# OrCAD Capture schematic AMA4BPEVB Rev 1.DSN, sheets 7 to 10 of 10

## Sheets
7 P08: Power Supply Tracker: size Custom
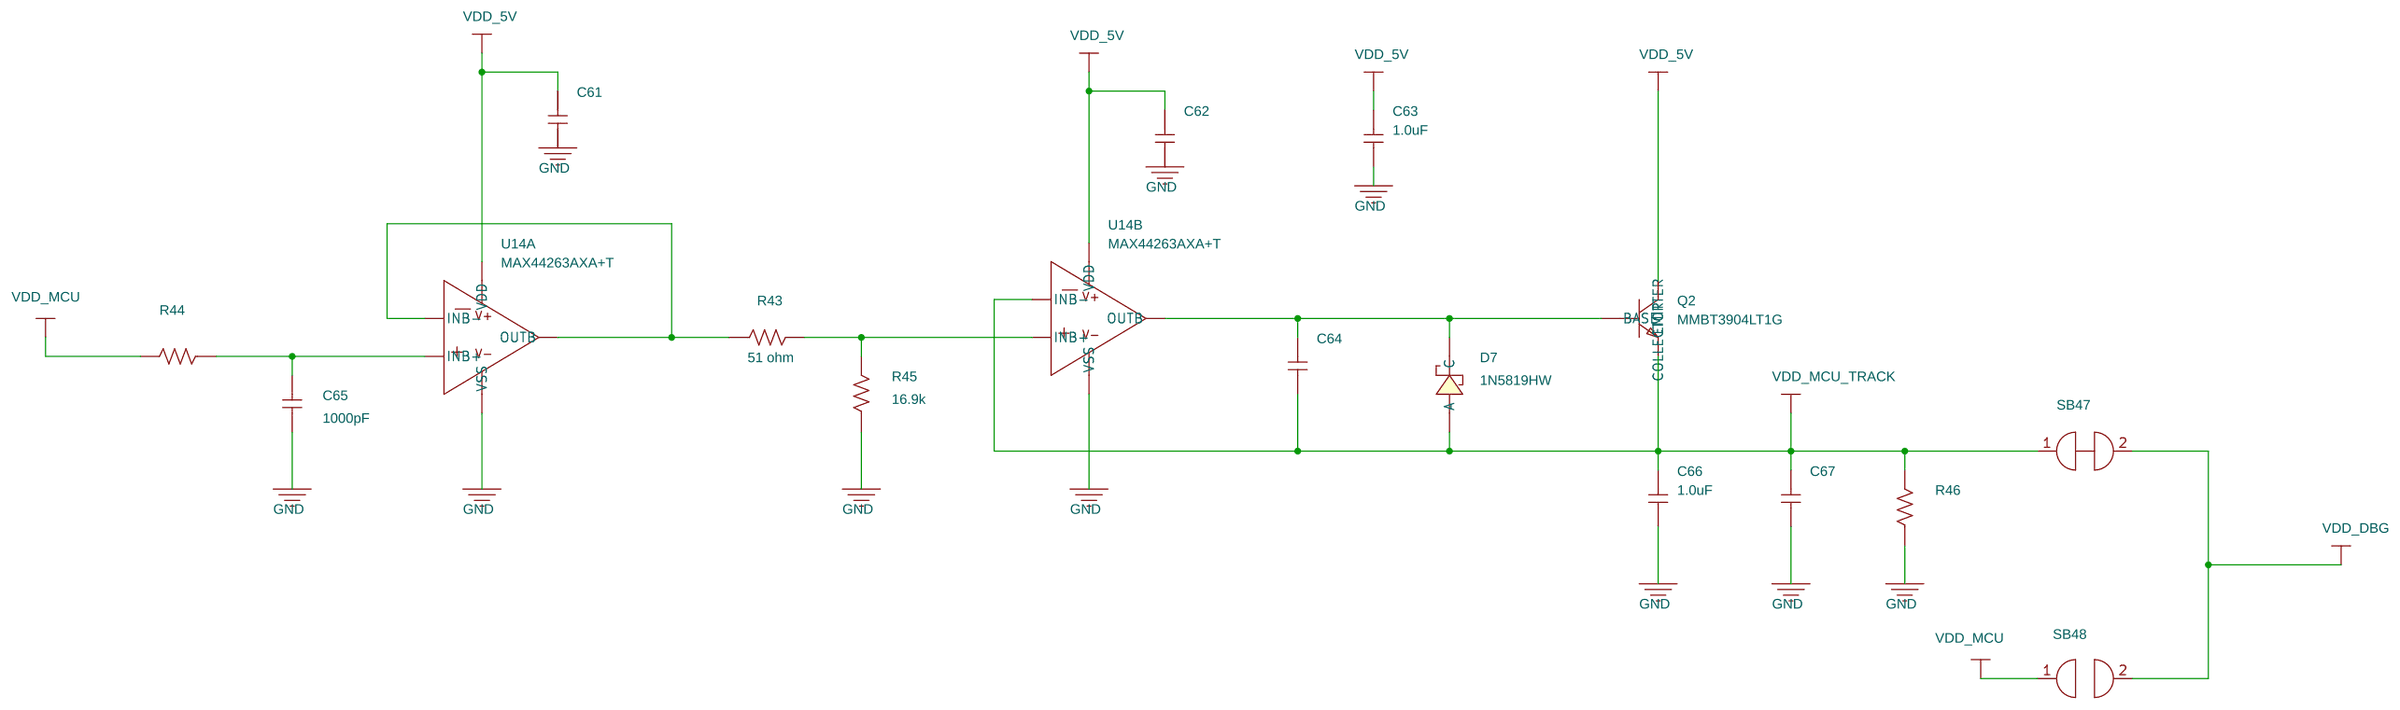
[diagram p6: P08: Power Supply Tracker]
8 P09: Audio Connections: size Custom
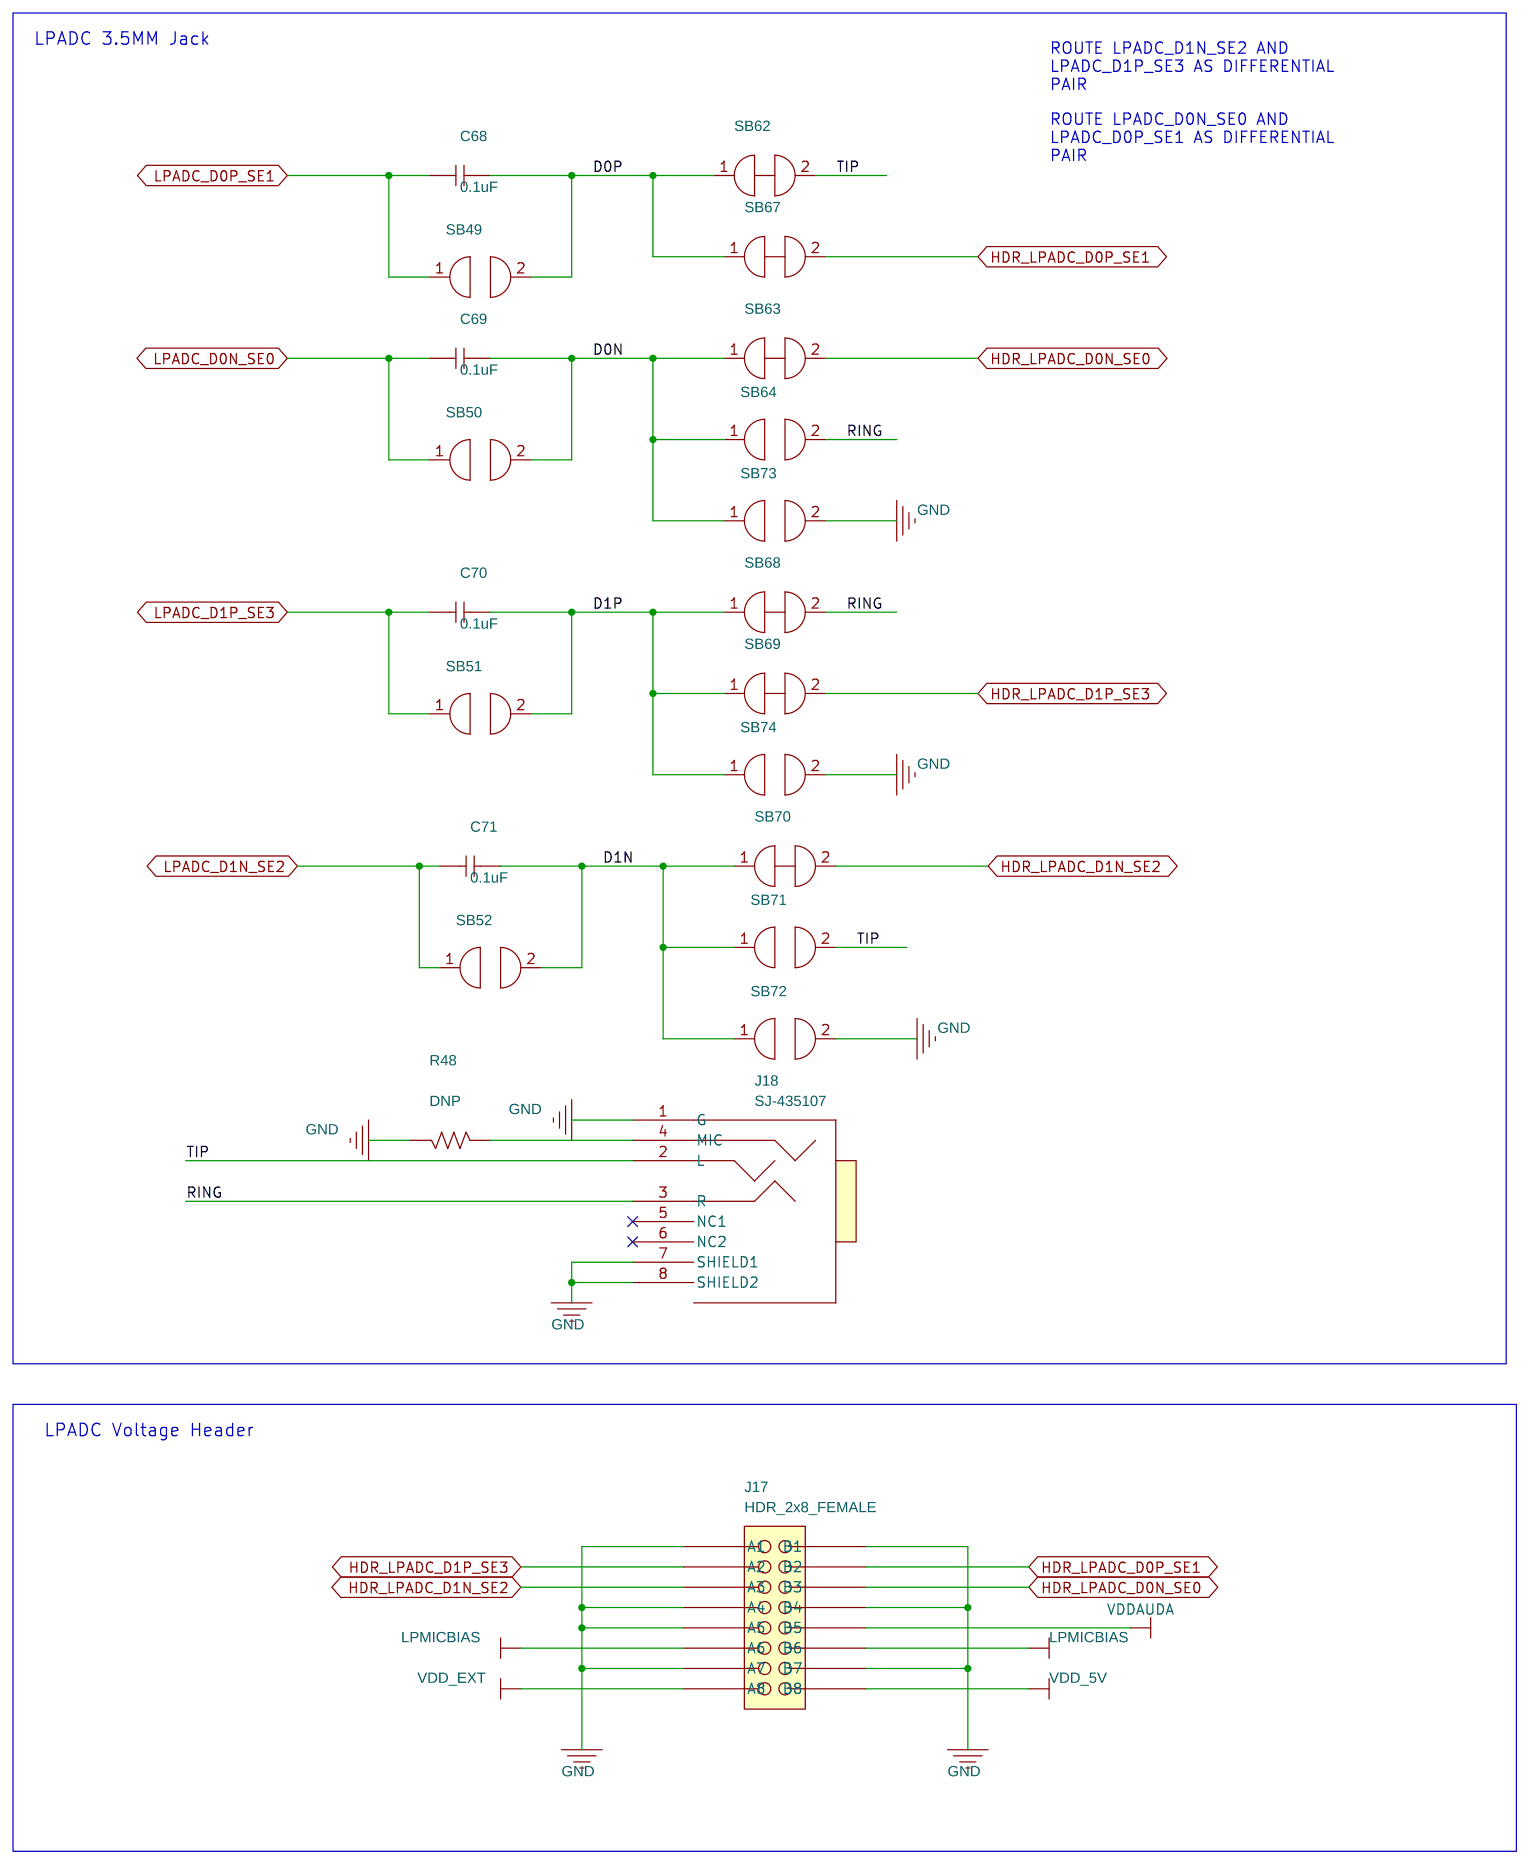
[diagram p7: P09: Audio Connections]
9 P02: Apollo 4 Blue Plus MCU: size Custom
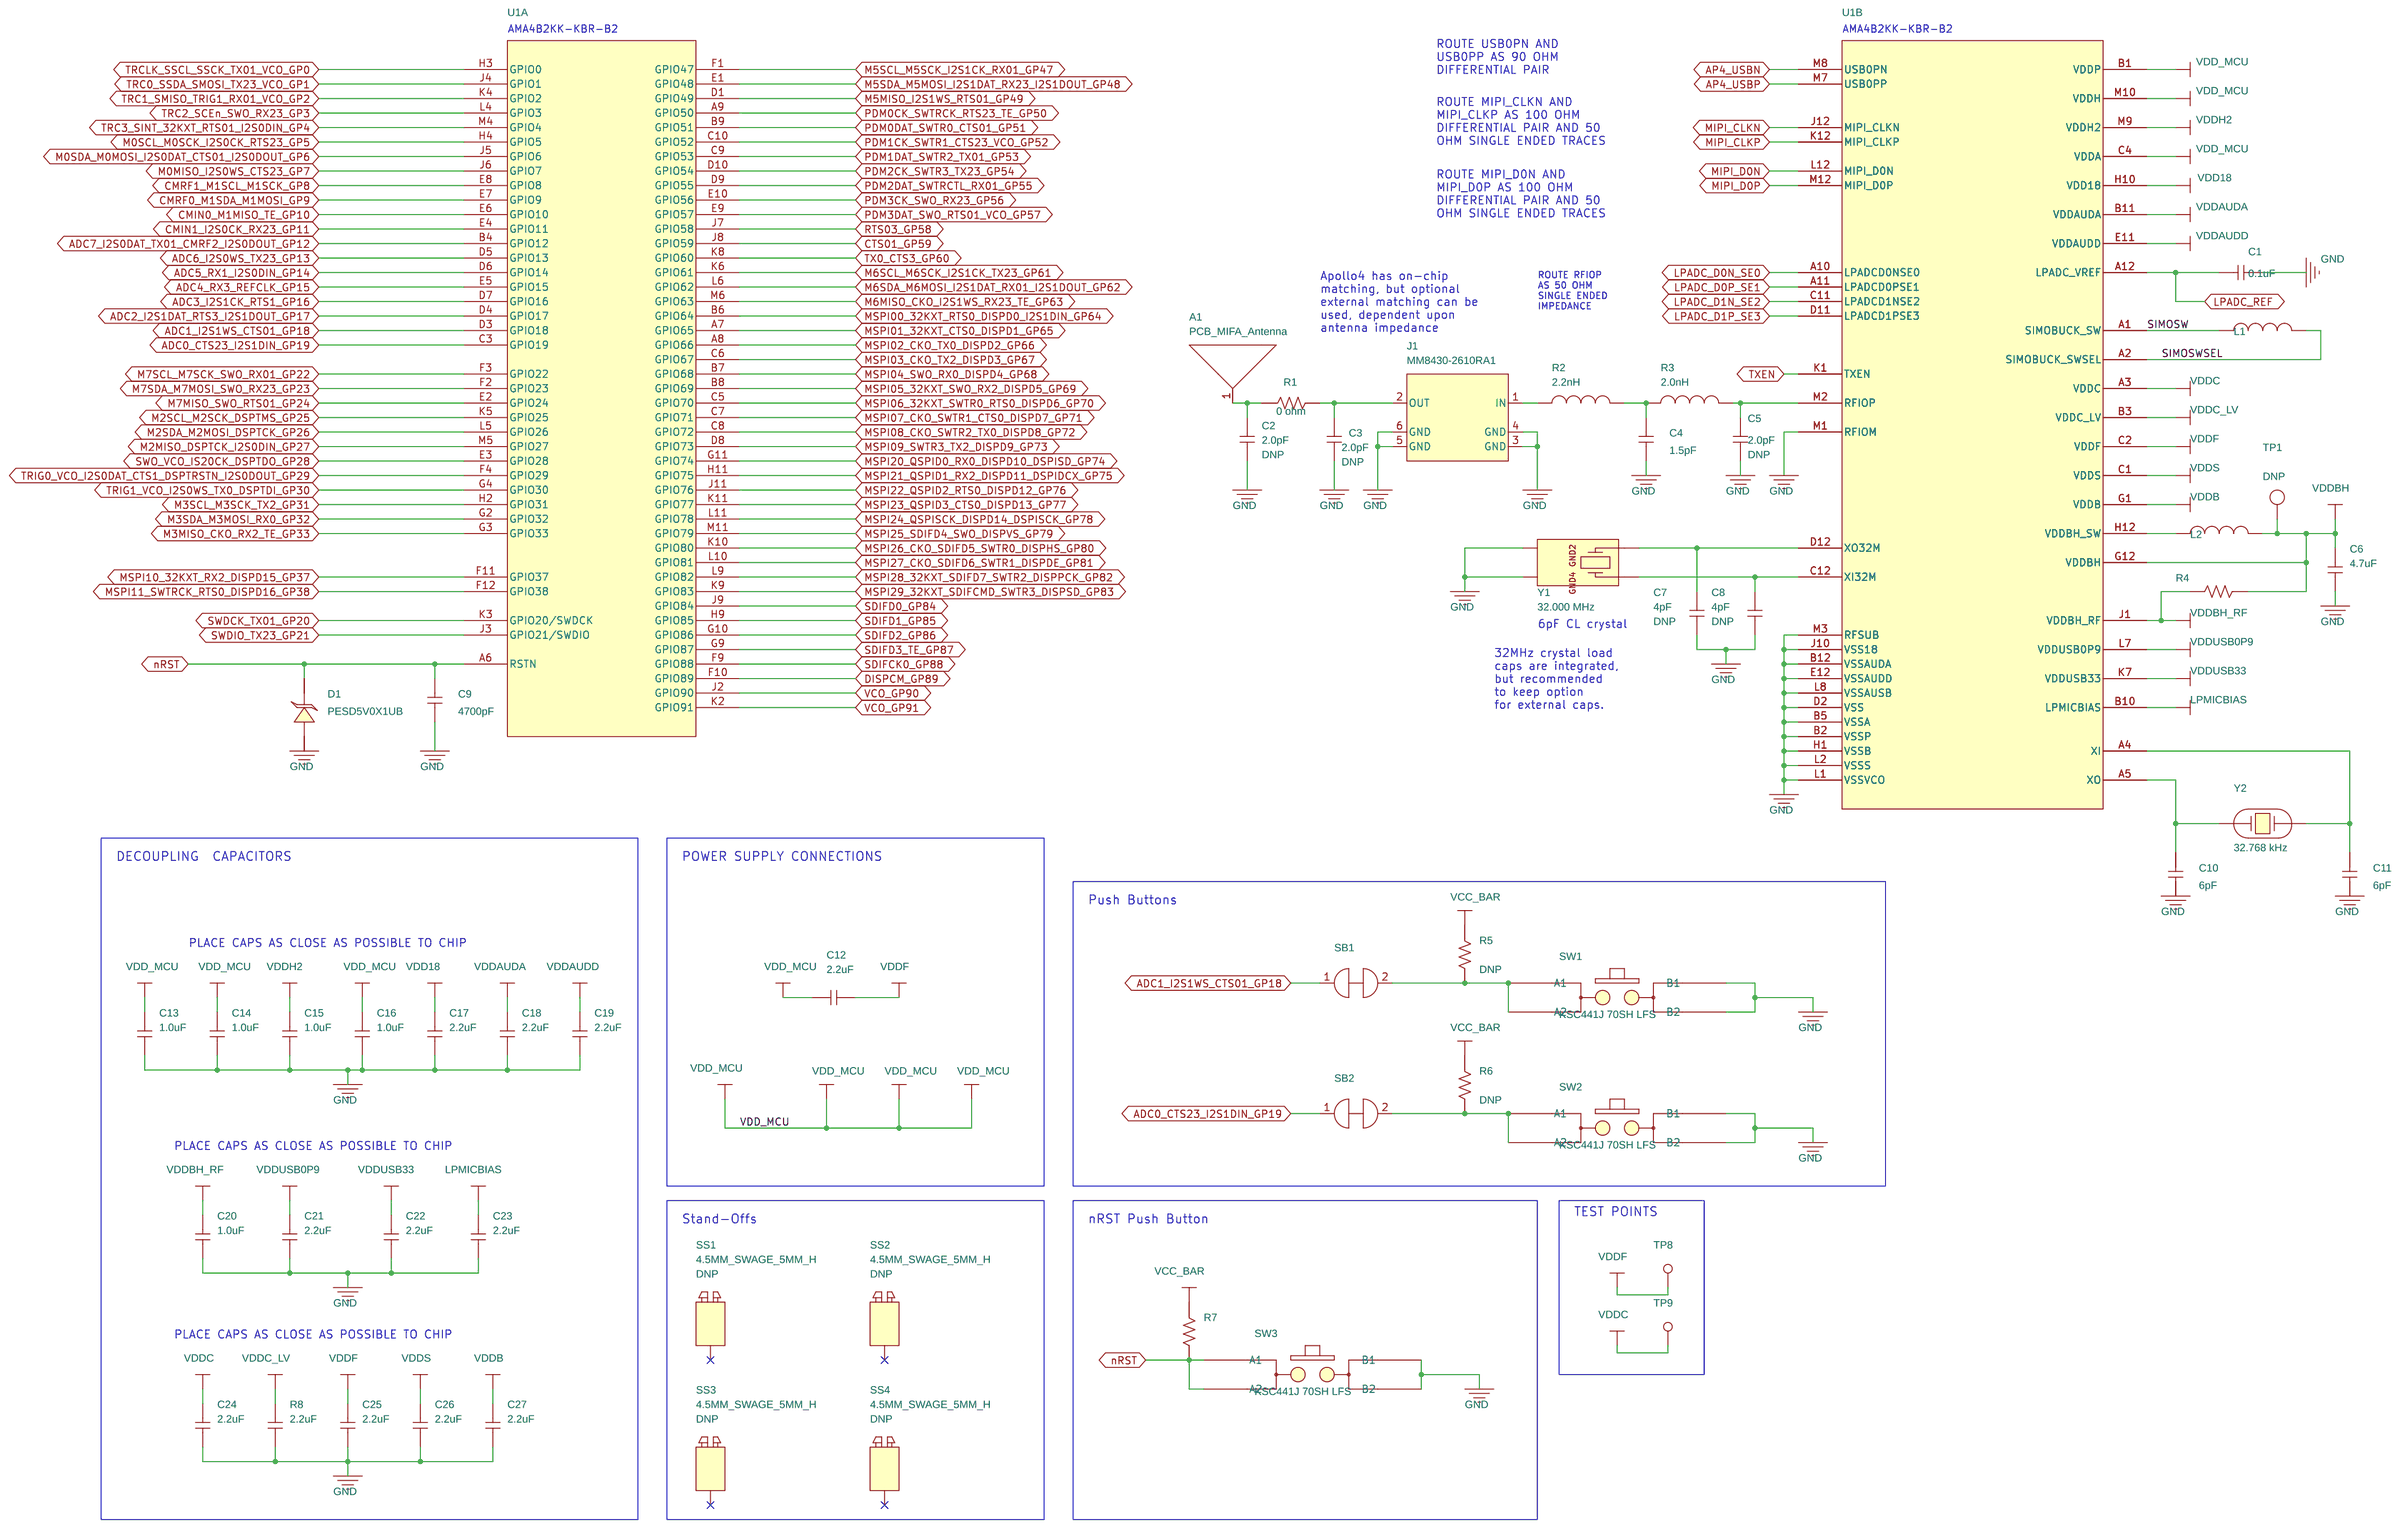
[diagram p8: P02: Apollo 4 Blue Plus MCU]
10 P07: Debug Headers and Support: size Custom
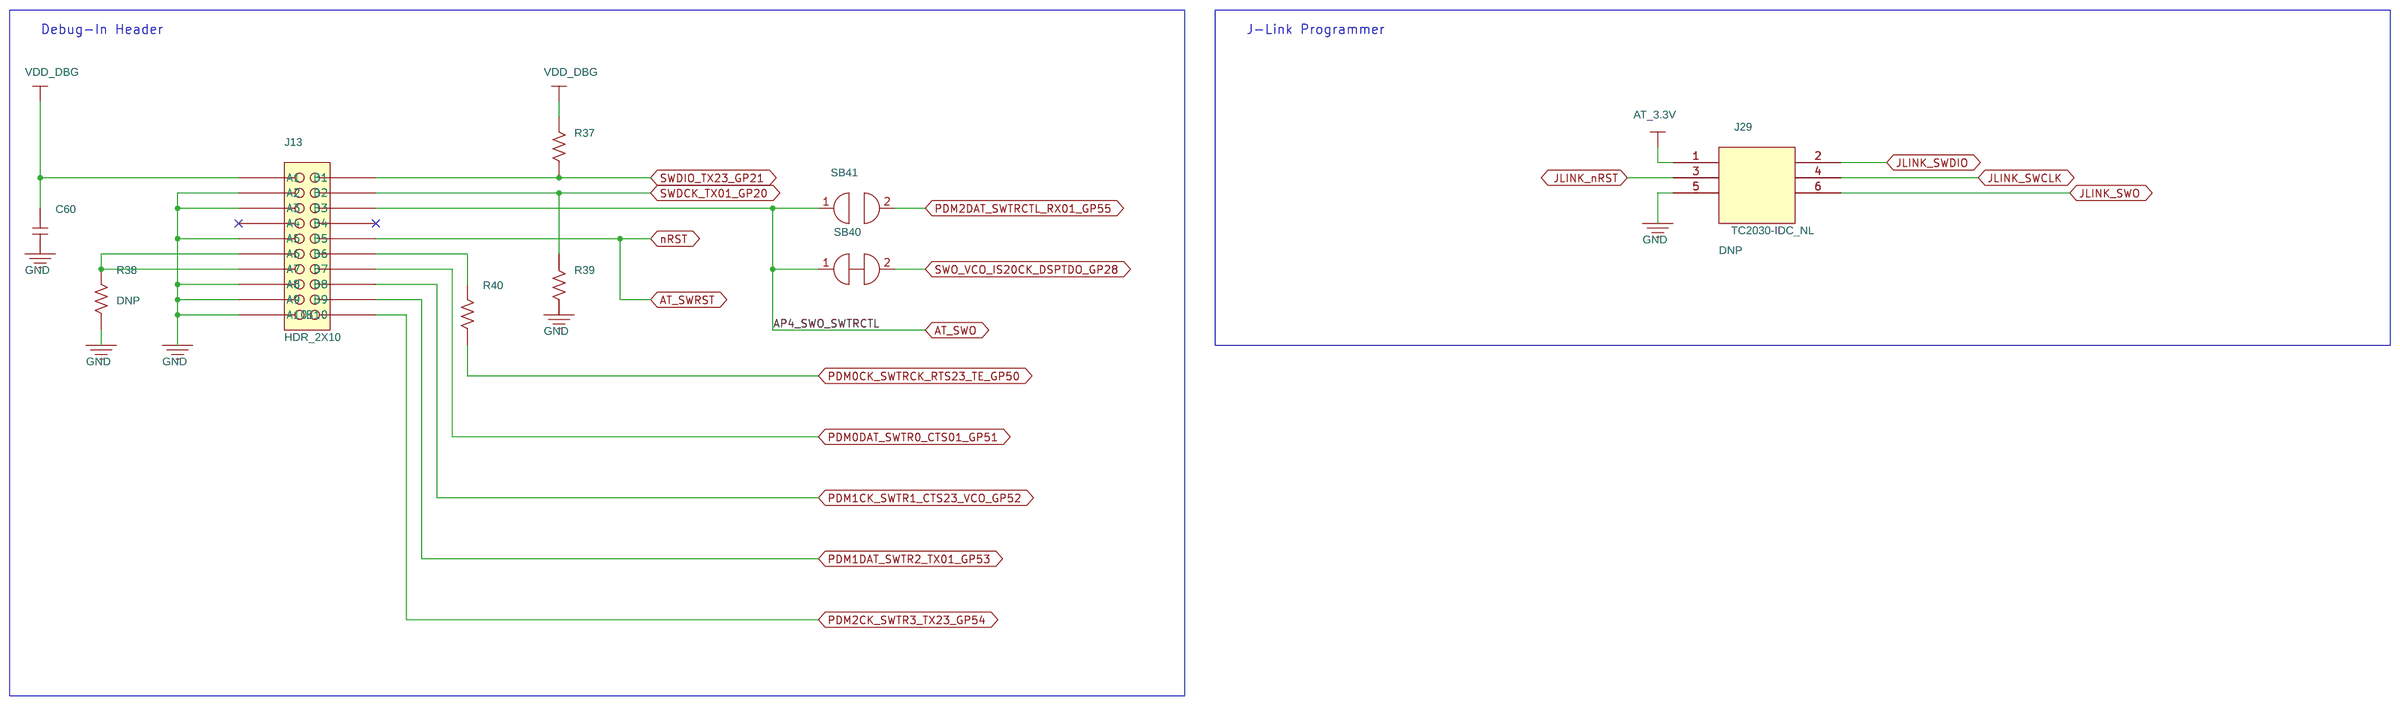
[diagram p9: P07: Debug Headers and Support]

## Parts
sheet P02: Apollo 4 Blue Plus MCU
A1  PCB_MIFA_Antenna  [PCB_MIFA_ANTENNA]
C1  0.1uF  [CC0201_HD]
C2  2.0pF  [CC0402_25]
C3  2.0pF  [CC0402_25]
C4  1.5pF  [RC0402_25]
C5  2.0pF  [CC0402_25]
C6  4.7uF  [CC0402_25]
C7  4pF  [CC0201_HD]
C8  4pF  [CC0201_HD]
C9  4700pF  [CC0201_HD]
C10  6pF  [CC0201_HD]
C11  6pF  [CC0201_HD]
C12  2.2uF  [CC0201_HD]
C13  1.0uF  [CC0201_HD]
C14  1.0uF  [CC0201_HD]
C15  1.0uF  [CC0201_HD]
C16  1.0uF  [CC0201_HD]
C17  2.2uF  [CC0201_HD]
C18  2.2uF  [CC0201_HD]
C19  2.2uF  [CC0201_HD]
C20  1.0uF  [CC0201_HD]
C21  2.2uF  [CC0201_HD]
C22  2.2uF  [CC0201_HD]
C23  2.2uF  [CC0201_HD]
C24  2.2uF  [CC0201_HD]
C25  2.2uF  [CC0201_HD]
C26  2.2uF  [CC0201_HD]
C27  2.2uF  [CC0201_HD]
D1  PESD5V0X1UB  [SC79]
J1  MM8430-2610RA1  [MM8430-2610]
L1  2.2uH  [0805_STR]
L2  1.0uH  [0603_CC]
R1  0 ohm  [RC0402_25]
R2  2.2nH  [RC0402_25]
R3  2.0nH  [RC0402_25]
R4  0 ohm  [CC0201_HD]
R5  100k  [RC0201]
R6  100k  [RC0201]
R7  100k  [RC0201]
R8  2.2uF  [CC0201_HD]
SB1  SB_SHORTED  [sb39x18_shorted]
SB2  SB_SHORTED  [sb39x18_shorted]
SS1  4.5MM_SWAGE_5MM_H  [spacer_150t]
SS2  4.5MM_SWAGE_5MM_H  [spacer_150t]
SS3  4.5MM_SWAGE_5MM_H  [spacer_150t]
SS4  4.5MM_SWAGE_5MM_H  [spacer_150t]
SW1  KSC441J 70SH LFS  [sw4_spst_7p7_sm]
SW2  KSC441J 70SH LFS  [sw4_spst_7p7_sm]
SW3  KSC441J 70SH LFS  [sw4_spst_7p7_sm]
TP1  TESTLOOP_LP  [test_loop]
TP8  35 MIL  [TESTPOINT_35MIL]
TP9  35 MIL  [TESTPOINT_35MIL]
U1  FALCON-SIP  [bga131_0p35_4p7x4p7]  (sections A,B)
Y1  32.000 MHz  [xtal4_1p6x1p2mm_sm]
Y2  32.768 kHz  [XTAL2-1p6x1p0-SM]
sheet P07: Debug Headers and Support
C60  1.0uF  [CC0201_HD]
J13  HDR_2X10  [HDR210_FTSH_SM]
J29  TC2030-IDC_NL  [TC2030-IDC]
R37  100k  [RC0201]
R38  0 ohm  [CC0201_HD]
R39  100k  [RC0201]
R40  0 ohm  [CC0201_HD]
SB40  SB_SHORTED  [sb39x18_shorted]
SB41  SB_OPEN  [sb39x18]
sheet P08: Power Supply Tracker
C61  0.1uF  [CC0201]
C62  0.1uF  [CC0201]
C63  1.0uF  [CC0201_HD]
C64  0.1uF  [CC0201]
C65  1000pF  [CC0402_25]
C66  1.0uF  [CC0201_HD]
C67  0.1uF  [CC0201]
D7  1N5819HW  [SOD123_112x67]
Q2  MMBT3904LT1G  [SOT23]
R43  51 ohm  [RC0402_25]
R44  10.0k  [RC0402_25]
R45  16.9k  [RC0402_25]
R46  10.0k  [RC0402_25]
SB47  SB_SHORTED  [sb39x18_shorted]
SB48  SB_OPEN  [sb39x18]
U14  MAX44263AXA+T  [SC70_8_2X2MM]  (sections A,B)
sheet P09: Audio Connections
C68  0.1uF  [CC0402_25]
C69  0.1uF  [CC0402_25]
C70  0.1uF  [CC0402_25]
C71  0.1uF  [CC0402_25]
J17  HDR_2x8_FEMALE  [SSM-108-L-DV-P]
J18  SJ-435107  [jack_stereo_ra_sj-435107]
R48  0 ohm  [CC0201_HD]
SB49  SB_OPEN  [sb39x18]
SB50  SB_OPEN  [sb39x18]
SB51  SB_OPEN  [sb39x18]
SB52  SB_OPEN  [sb39x18]
SB62  SB_SHORTED  [sb39x18_shorted]
SB63  SB_SHORTED  [sb39x18_shorted]
SB64  SB_OPEN  [sb39x18]
SB67  SB_SHORTED  [sb39x18_shorted]
SB68  SB_SHORTED  [sb39x18_shorted]
SB69  SB_SHORTED  [sb39x18_shorted]
SB70  SB_SHORTED  [sb39x18_shorted]
SB71  SB_OPEN  [sb39x18]
SB72  SB_OPEN  [sb39x18]
SB73  SB_OPEN  [sb39x18]
SB74  SB_OPEN  [sb39x18]

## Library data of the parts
A1 = PCB_MIFA_ANTENNA: Meandering Inverted F PCB Trace Antenna; AMBIQ_PN: AM-09-0336; ASSY_OPT: DNP; PART_TYPE: MISC; ROHS: Yes; STATUS: Production
C1 = CAP_NP: CAP CER 0.1uF 10V +/- 10% X5R 0201; AMBIQ_PN: AM-02-1127; DISTRIBUTOR: DIGIKEY; DISTRIBUTOR_PN: 478-10051-2-ND; Dielectric Material: X5R; HEIGHT: 0.33MM; LEAD_FREE: Yes; MFG_NAME: AVX; MFG_PN: 0201ZD104KAT2A; Manufacturer_Datasheet: http://datasheets.avx.com/cx5r.pdf; PART_TYPE: CER\0201; Package Size: 0201; Package Type: SMD; ROHS: Yes; STATUS: Production; TOL: 10%; VOLTAGE: 10V
C2 C3 C5 = CAP_NP: CAP CER 2.0pF 50V +/-0.05pF COG 0402; AMBIQ_PN: AM-02-1085; ASSY_OPT: DNP; DISTRIBUTOR: MOUSER; DISTRIBUTOR_PN: 81-GRM1555C1H2R0WA1D; Dielectric Material: COG; HEIGHT: 0.55MM; LEAD_FREE: Yes; MFG_NAME: MURATA; MFG_PN: GRM1555C1H2R0WA01D; Manufacturer_Datasheet: http://search.murata.co.jp/Ceramy/image/img/A01X/G101/ENG/GRM1555C1H2R0WA01-01.pdf; PART_TYPE: CER\0402; Package Size: 0402; Package Type: SMD; ROHS: Yes; STATUS: Production; TOL: +/-0.05pF; VOLTAGE: 50V
C4 = CAP_NP: CaP CER 1.5pF 50V +/-0.25pF C0G 0402; AMBIQ_PN: AM-02-1126; DISTRIBUTOR: MOUSER; DISTRIBUTOR_PN: 81-GRM1555C1H1R5CA1D; Dielectric Material: C0G; HEIGHT: 0.55MM; LEAD_FREE: Yes; MFG_NAME: MURATA; MFG_PN: GRM1555C1H1R5CA01D; Manufacturer_Datasheet: https://search.murata.co.jp/Ceramy/image/img/A01X/G101/ENG/GRM1555C1H1R5CA01-01A.pdf; PART_TYPE: CER\0402; Package Size: 0402; Package Type: SMD; ROHS: Yes; STATUS: Production; TOL: +/-0.25pF; VOLTAGE: 50V
C6 = CAP_NP: CAP CER 4.7UF 10V 10% X5R 0402; AMBIQ_PN: AM-02-1107; DISTRIBUTOR: DIGIKEY; DISTRIBUTOR_PN: 490-13252-1-ND; Dielectric Material: X5R; HEIGHT: 0.80MM; LEAD_FREE: Yes; MFG_NAME: MURATA; MFG_PN: ZRB15XR61A475KE01D; Manufacturer_Datasheet: https://www.digikey.com/product-detail/en/murata-electronics-north-america/ZRB15XR61A475KE01D/490-13252-1-ND/5877460; PART_TYPE: CER\0402; Package Size: 0402; Package Type: SMD; ROHS: Yes; STATUS: Production; TOL: 10%; VOLTAGE: 10V
C7 C8 = CAP_NP: CAP CER 4pF 50V 2.5% COG 0201; AMBIQ_PN: AM-02-1094; ASSY_OPT: DNP; DISTRIBUTOR: MOUSER; DISTRIBUTOR_PN: 81-GRM0335C1H4R0BA1D; Dielectric Material: COG; HEIGHT: 0.33MM; LEAD_FREE: Yes; MFG_NAME: MURATA; MFG_PN: GRM0335C1H4R0BA01D; Manufacturer_Datasheet: http://www.murata.com/~/media/webrenewal/support/library/catalog/products/capacitor/mlcc/c02e.pdf; PART_TYPE: CER\0201; Package Size: 0201; Package Type: SMD; ROHS: Yes; STATUS: Production; TOL: 2.5%; VOLTAGE: 50V
C9 = CAP_NP: CAP CER 4700PF 25V 10% X5R CC0201; AMBIQ_PN: AM-02-1120; DISTRIBUTOR: MOUSER; DISTRIBUTOR_PN: 81-GRM33R61E472KA12D; Dielectric Material: X5R; HEIGHT: 0.33MM; LEAD_FREE: Yes; MFG_NAME: MURATA; MFG_PN: GRM033R61E472KA12D; Manufacturer_Datasheet: https://search.murata.co.jp/Ceramy/image/img/A01X/G101/ENG/GRM033R61E472KA12-01.pdf; PART_TYPE: CER\0201; Package Size: 0201; Package Type: SMD; ROHS: Yes; STATUS: Production; TOL: 10%; VOLTAGE: 25V
C10 C11 = CAP_NP: CAP CER 6pF 50V +/-0.1pF C0G 0201; AMBIQ_PN: AM-02-1123; DISTRIBUTOR: DIGIKEY; DISTRIBUTOR_PN: 490-11339-2-ND; Dielectric Material: C0G; HEIGHT: 0.33MM; LEAD_FREE: Yes; MFG_NAME: MURATA; MFG_PN: GRM0335C1H6R0BA01D; Manufacturer_Datasheet: https://search.murata.co.jp/Ceramy/image/img/A01X/G101/ENG/GRM0335C1H6R0BA01-01.pdf; PART_TYPE: CER\0201; Package Size: 0201; Package Type: SMD; ROHS: Yes; STATUS: Production; TOL: +/-0.1pF; VOLTAGE: 50V
C12 C17-C19 C21-C27 R8 = CAP_NP: CAP CER 2.2UF 10V 10% X5R 0201; AMBIQ_PN: AM-02-1106; DISTRIBUTOR: DIGIKEY; DISTRIBUTOR_PN: 490-13227-2-ND; Dielectric Material: X5R; HEIGHT: 0.39MM; LEAD_FREE: Yes; MFG_NAME: MURATA; MFG_PN: GRM033R61A225KE47D; Manufacturer_Datasheet: http://psearch.en.murata.com/capacitor/product/GRM033R61A225KE47%23.pdf; PART_TYPE: CER\0201; Package Size: 0201; Package Type: SMD; ROHS: Yes; STATUS: Production; TOL: 10%; VOLTAGE: 10V
C13-C16 C20 C63 C66 = CAP_NP: CAP CER 1.0UF 10V 20% X6S 0201; AMBIQ_PN: AM-02-1091; DISTRIBUTOR: MOUSER; DISTRIBUTOR_PN: 81-GRM033C81A105ME5D; Dielectric Material: X6S; HEIGHT: 0.33MM; LEAD_FREE: Yes; MFG_NAME: MURATA; MFG_PN: GRM033C81A105ME05D; Manufacturer_Datasheet: http://psearch.en.murata.com/capacitor/product/GRM033C81A105ME05%23.pdf; PART_TYPE: CER\0201; Package Size: 0201; Package Type: SMD; ROHS: Yes; STATUS: Production; TOL: 20%; VOLTAGE: 10V
D1 = DIODE_TVS: DIODE TVS 5.5V STANDOFF 8V BREAKDOWN SC79; AMBIQ_PN: AM-05-0472; DISTRIBUTOR: DIGIKEY; DISTRIBUTOR_PN: 568-7540-1-ND; HEIGHT: 0.65MM; LEAD_FREE: Yes; MFG_NAME: NXP SEMICONDUCTOR; MFG_PN: PESD5V0X1UB,135; Manufacturer_Datasheet: http://www.nxp.com/documents/data_sheet/PESD5V0X1UB.pdf; PART_TYPE: DIODE\TVS; ROHS: Yes; Rated Current: 1.5A; Rated Voltage: 10V; STATUS: Production
J1 = MM8430-2610: CON COAX 50-Ohm INTERNAL SWITCH SMD; AMBIQ_PN: AM-03-1293; DISTRIBUTOR: DIGIKEY; DISTRIBUTOR_PN: 490-4980-1-ND; HEIGHT: 1.9MM; LEAD_FREE: Yes; MFG_NAME: MURATA; Manufacturer_Datasheet: https://www.mouser.com/datasheet/2/281/o33e-844855.pdf; PART_TYPE: COAX; Package Type: SMD; ROHS: Yes; STATUS: Production
L1 = INDUCTOR: IND POWER 2.2uH 0.228OHM 1.2A 2A-SAT SMT; AMBIQ_PN: AM-08-0416; DISTRIBUTOR: MOUSER; DISTRIBUTOR_PN: 81-DFE201210U-2R2MP2; HEIGHT: 1.00MM; LEAD_FREE: Yes; MFG_NAME: MURATA; MFG_PN: DFE201210U-2R2M=P2; Manufacturer_Datasheet: http://psearch.en.murata.com/inductor/product/DFE201210U-2R2M%23.html; PEAK_REFLOW_TEMP: 260; Package Size: 0805; ROHS: Yes; Rated Current: 1.2A; STATUS: Production; TOL: 20%
L2 = INDUCTOR: IND POWER 1.0uH 0.144OHM 1.6A 2A-SAT SMT; AMBIQ_PN: AM-08-0415; DISTRIBUTOR: MOUSER; DISTRIBUTOR_PN: 81-DFE18SAN1R0ME0L; HEIGHT: 0.80MM; LEAD_FREE: Yes; MFG_NAME: MURATA; MFG_PN: DFE18SAN1R0ME0L; Manufacturer_Datasheet: http://psearch.en.murata.com/inductor/product/DFE18SAN1R0ME0%23.html; PEAK_REFLOW_TEMP: 260; Package Size: 0603; ROHS: Yes; Rated Current: 2A; STATUS: Production; TOL: 20%
R1 = RES: RES TF ZERO  OHM 1/10W RC0402; AMBIQ_PN: AM-01-2916; DISTRIBUTOR: MOUSER; DISTRIBUTOR_PN: 667-ERJ-2GE0R00X / 667-ERJ-2GE0R00X; HEIGHT: 0.40 MM; LEAD_FREE: Yes; MFG_NAME: PANASONIC; MFG_PN: ERJ-2GE0R00X; Manufacturer_Datasheet: https://industrial.panasonic.com/ww/products/resistors/chip-resistors/general; PART_TYPE: 0402; Power Rating (Max) (W): 1/10W; ROHS: Yes; STATUS: Production; TOL: 5%; Type: SMD
R2 = INDUCTOR: IND RF 2.2nH  0402 +/-0.1nH; AMBIQ_PN: AM-08-0421; DISTRIBUTOR: DIGIKEY; DISTRIBUTOR_PN: 490-1128-2-ND; HEIGHT: 0.45MM; LEAD_FREE: Yes; MFG_NAME: MURATA; MFG_PN: LQP15MN2N2B02D; Manufacturer_Datasheet: https://search.murata.co.jp/Ceramy/image/img/P02/JELF243C-0007.pdf; Package Size: 0402; ROHS: Yes; Rated Current: 0.22A; STATUS: Production; TOL: +/-0.1nH
R3 = INDUCTOR: IND RF 2.0nH 0402 +/- 0.1nH; AMBIQ_PN: AM-08-0422; DISTRIBUTOR: DIGIKEY; DISTRIBUTOR_PN: 490-6752-2-ND; HEIGHT: 0.45MM; Inductance (Nominal) (H): 2nH; LEAD_FREE: Yes; MFG_NAME: MURATA; MFG_PN: LQP15MN2N0B02D; Manufacturer_Datasheet: https://search.murata.co.jp/Ceramy/image/img/P02/JELF243C-0007.pdf; Package Size: 0402; ROHS: Yes; Rated Current: 0.22A; STATUS: Production; TOL: +/-0.1nH
R4 R40 = RES: RES TF ZERO OHM 1/20W 1% 0201; AMBIQ_PN: AM-01-0014; DISTRIBUTOR: DIGIKEY; DISTRIBUTOR_PN: P0.0AGDKR-ND; HEIGHT: 0.30 MM; LEAD_FREE: Yes; MFG_NAME: PANASONIC; MFG_PN: ERJ-1GE0R00C; Manufacturer_Datasheet: http://industrial.panasonic.com/www-data/pdf/AOA0000/AOA0000CE2.pdf; NUM_RESISTORS: 1; PART_TYPE: 0201; PCB_FOOTPRINT_OPTIONS: RC0201,RC0201_X2,RC0201_CC; PEAK_REFLOW_TEMP: 260; Power Rating (Max) (W): 1/20W; ROHS: Yes; STATUS: Production; TOL: 1%; Type: SMD
R5 R6 = RES: RES TF 100K OHM 1% 1/20W 0201; AMBIQ_PN: AM-01-2915; ASSY_OPT: DNP; DISTRIBUTOR: MOUSER; DISTRIBUTOR_PN: 667-ERJ-1GNF1003C; FPLIST: RC0201,RC0201_CC; HEIGHT: 0.26 MM; LEAD_FREE: Yes; MFG_NAME: PANASONIC; MFG_PN: ERJ-1GNF1003C; Manufacturer_Datasheet: http://www.mouser.com/ds/2/315/AOA0000C304-1149620.pdf; Material (Resistor): TF; NUM_RESISTORS: 1; PART_TYPE: 0201; PCB_FOOTPRINT_OPTIONS: RC0201,RC0201_CC; PEAK_REFLOW_TEMP: 260; Power Rating (Max) (W): 1/20W; ROHS: Yes; STATUS: Production; TOL: 1%; Type: SMD
R7 R37 R39 = RES: RES TF 100K OHM 1% 1/20W 0201; AMBIQ_PN: AM-01-2915; DISTRIBUTOR: MOUSER; DISTRIBUTOR_PN: 667-ERJ-1GNF1003C; FPLIST: RC0201,RC0201_CC; HEIGHT: 0.26 MM; LEAD_FREE: Yes; MFG_NAME: PANASONIC; MFG_PN: ERJ-1GNF1003C; Manufacturer_Datasheet: http://www.mouser.com/ds/2/315/AOA0000C304-1149620.pdf; Material (Resistor): TF; NUM_RESISTORS: 1; PART_TYPE: 0201; PCB_FOOTPRINT_OPTIONS: RC0201,RC0201_CC; PEAK_REFLOW_TEMP: 260; Power Rating (Max) (W): 1/20W; ROHS: Yes; STATUS: Production; TOL: 1%; Type: SMD
SB1 SB2 SB40 SB47 SB62 SB63 SB67-SB70 = SB_Shorted: Solder-Bridge, Shorted, 39X18 PAD; AMBIQ_PN: AM-03-1291; ASSY_OPT: DNP; PART_TYPE: MISC; ROHS: Yes; STATUS: Production
SS1-SS4 = SPACER: FASTENER, STANDOFF 4.5MM RD X 5MM X M2.5 THD; AMBIQ_PN: AM-06-0041; ASSY_OPT: DNP; DISTRIBUTOR: DIGIKEY; DISTRIBUTOR_PN: 1772-4027-ND; HEIGHT: 5.0MM; LEAD_FREE: Yes; MFG_NAME: RAF ELECTRONIC HARDWARE; MFG_PN: M1502-B-2545-B; Manufacturer_Datasheet: https://cadlinks.rafhdwe.com/dk2d/M1502-b-2545-b/; ROHS: Yes; STATUS: Production
SW1-SW3 = SW_PB_ESW: SW SPST PB MOM ON SMT 32V 50MA J-BEND YELLOW; AMBIQ_PN: AM-09-0322; DISTRIBUTOR: DIGIKEY; HEIGHT: 4.3MM; LEAD_FREE: Yes; MFG_NAME: C&K COMPONENTS; Manufacturer_Datasheet: http://www.ck-components.com/index.php?module=media&action=Display&cmpref=14422&lang=en&width=&height=&format=&alt=; PART_TYPE: SWITCHES\MOM/SM; ROHS: Yes; STATUS: Production
TP1 = TestLoop: TEST POINT PC LOW PRO W/OUT BASE; AMBIQ_PN: AM-03-1228; ASSY_OPT: DNP; DISTRIBUTOR: DIGIKEY; DISTRIBUTOR_PN: 5021KCT-ND; HEIGHT: 2.54MM; LEAD_FREE: Yes; MFG_NAME: KEYSTONE ELECTRONICS; MFG_PN: 5021; Manufacturer_Datasheet: http://www.keyelco.com/product-pdf.cfm?p=1325; Number Of Connectors: 1; Number Of Contact Rows: 1; Number Of Contacts: 1; PART_TYPE: TEST_POINT; ROHS: Yes; STATUS: Production; Type: TEST_POINT
TP8 TP9 = Test_pad: TEST PAD 35 MIL ROUND SMT; NO PART TO ORDER; AMBIQ_PN: AM-09-0040; HEIGHT: 0.1 MM; LEAD_FREE: Yes; PART_TYPE: TESTPOINT; ROHS: Yes; STATUS: Production
U1 = FALCON-SIP: IC FALCON ULTRA LOW POWER MCU BLE 1.8-3.6V BGA144; HEIGHT: 0.8MM; IC Type: ULTRA LOW POWER MCU BLE; LEAD_FREE: Yes; MFG_NAME: AMBIQ MICRO; MFG_PN: APOLLO4-SIP; PART_TYPE: MCU BLE; ROHS: Yes; STATUS: Production
Y1 = XTAL4_GND24: XTAL 32MHZ 6pF 10ppm  1.6mm x 1.2mm x 0.4mm SMT; AMBIQ_PN: AM-04-0350; DISTRIBUTOR: MOUSER; DISTRIBUTOR_PN: 815-12W32-6D1XT; Frequency: 32.768 kHz; HEIGHT: 0.40MM; LEAD_FREE: Yes; MFG_NAME: ABRACON CORP; MFG_PN: ABM12W-32.0000MHZ-6-D1X-T3; Manufacturer_Datasheet: https://abracon.com/Resonators/ABM12W.pdf; PART_TYPE: CRYSTAL; ROHS: Yes; STATUS: Production; Type: SMD
Y2 = XTAL: XTAL 32.768KHZ 7.0pF 20ppm 1.6mm x 1.0mm SMT; AMBIQ_PN: AM-04-0342; DISTRIBUTOR: MOUSER; DISTRIBUTOR_PN: 717-9HT12-32.76KDZYT; HEIGHT: 0.50MM; LEAD_FREE: Yes; MFG_NAME: TXC; MFG_PN: 9HT12-32.768KDZY; Manufacturer_Datasheet: http://www.txccorp.com/download/products/quartz_crystals/2015TXC_9HT12_29.pdf; PART_TYPE: CRYSTAL; ROHS: Yes; STATUS: Production; Type: SMD
C60 = CAP_NP: CAP CER 1.0UF 10V 20% X6S 0201; AMBIQ_PN: AM-02-1091; BIAS_25%: 0.60uF; BIAS_50%: 0.39uF; BIAS_75%: 0.25uF; DISTRIBUTOR: MOUSER; DISTRIBUTOR_PN: 81-GRM033C81A105ME5D; Dielectric Material: X6S; FPLIST: CC0201,CC0201_HD,CC0201_3PIN,CC0201_CC; HEIGHT: 0.33MM; LEAD_FREE: Yes; MFG_NAME: MURATA; MFG_PN: GRM033C81A105ME05D; Manufacturer_Datasheet: http://psearch.en.murata.com/capacitor/product/GRM033C81A105ME05%23.pdf; PART_TYPE: CER\0201; PCB_FOOTPRINT_OPTIONS: CC0201,CC0201_HD,CC0201_3PIN,CC0201_CC; PEAK_REFLOW_TEMP: 260; Package Size: 0201; Package Type: SMD; ROHS: Yes; STATUS: Production; TOL: 20%; Temp Coefficient (ppm/Deg C): X6S; VOLTAGE: 10V
J13 = CONN_HDR_10X2: CONN HEAD 2X10 SMD .50x.50 KEYED; AMBIQ_PN: AM-03-1282; DISTRIBUTOR: DIGIKEY; DISTRIBUTOR_PN: SAM13177TR-ND; HEIGHT: 5.71M; LEAD_FREE: Yes; MFG_NAME: SAMTEC; MFG_PN: FTSH-110-01-L-DV-K-P-TR; Manufacturer_Datasheet: http://www.samtec.com/ftppub/pdf/FTSH_SMT.PDF; PART_TYPE: HEADER; Package Type: SMD; ROHS: Yes; STATUS: Production
J29 = TC2030-IDC-NL: Cbl Plug-Of-Nails 6-Pin w/o Legs; AMBIQ_PN: AM-03-1304; ASSY_OPT: DNP; DISTRIBUTOR: DIGIKEY; DISTRIBUTOR_PN: TC2030-IDC-ND; MFG_NAME: TAG-CONNECT; Package Type: SMD; ROHS: Yes; STATUS: Production
R38 R48 = RES: RES TF ZERO OHM 1/20W 1% 0201; AMBIQ_PN: AM-01-0014; ASSY_OPT: DNP; DISTRIBUTOR: DIGIKEY; DISTRIBUTOR_PN: P0.0AGDKR-ND; HEIGHT: 0.30 MM; LEAD_FREE: Yes; MFG_NAME: PANASONIC; MFG_PN: ERJ-1GE0R00C; Manufacturer_Datasheet: http://industrial.panasonic.com/www-data/pdf/AOA0000/AOA0000CE2.pdf; NUM_RESISTORS: 1; PART_TYPE: 0201; PCB_FOOTPRINT_OPTIONS: RC0201,RC0201_X2,RC0201_CC; PEAK_REFLOW_TEMP: 260; Power Rating (Max) (W): 1/20W; ROHS: Yes; STATUS: Production; TOL: 1%; Type: SMD
SB41 SB48-SB52 SB64 SB71-SB74 = SB_Open: Solder-Bridge, No Connect, 39X18 PAD; AMBIQ_PN: AM-03-1290; ASSY_OPT: DNP; PART_TYPE: MISC; ROHS: Yes; STATUS: Production
C61 C62 C64 C67 = CAP_NP: CAP CER 0.1UF 10V 10% X5R 0201; AMBIQ_PN: AM-02-1050; DISTRIBUTOR: DIGIKEY; DISTRIBUTOR_PN: 587-2241-1-ND; Dielectric Material: X5R; HEIGHT: 0.33MM; LEAD_FREE: Yes; MFG_NAME: TAIYO YUDEN; MFG_PN: LMK063BJ104KP-F; Manufacturer_Datasheet: http://www.yuden.co.jp/or/product/category/capacitor/LMK063BJ104KP-F.pdf; PART_TYPE: CER\0201; PCB_FOOTPRINT_OPTIONS: CC0402_25,CC0402_HD,CC0402_CC; PEAK_REFLOW_TEMP: 260; Package Size: 0201; Package Type: SMD; ROHS: Yes; STATUS: Production; TOL: 10%; VOLTAGE: 10V
C65 = CAP_NP: CAP CER 1000PF 50V X7R 5% 0402; AMBIQ_PN: AM-02-0295; Dielectric Material: X7R; HEIGHT: 0.6MM; LEAD_FREE: Yes; MFG_NAME: CAPAX TECHNOLOGIES INC.; MFG_PN: 0402X102J500SNT; Manufacturer_Datasheet: http://www.calchipelectronics.com/pdf/gmc_series.pdf; PART_TYPE: CER\0402; Package Size: 0402; Package Type: Tape&reel; ROHS: Yes; STATUS: Production; TOL: 5%
D7 = DIODE_SCHTKY: DIODE SCH RECT 1A 40V SOD123; AMBIQ_PN: AM-05-0502; DISTRIBUTOR: DIGIKEY; DISTRIBUTOR_PN: 1N5819HW-FDICT-ND; HEIGHT: 1.35MM; LEAD_FREE: Yes; MFG_NAME: DIODES INC; MFG_PN: 1N5819HW-7-F; Manufacturer_Datasheet: https://www.diodes.com/assets/Datasheets/ds30217.pdf; PART_TYPE: DIODE\SCHOTTKY; ROHS: Yes; Rated Current: 1A; STATUS: Production
Q2 = NPN: TRAN NPN GEN 200MA 40V SOT-23; AMBIQ_PN: AM-05-0319; HEIGHT: 1.11 MM; LEAD_FREE: Yes; MFG_NAME: ON SEMICONDUCTOR; Manufacturer_Datasheet: http://www.onsemi.com/pub/Collateral/MMBT3904LT1-D.PDF; PART_TYPE: TRANSISTOR\BJT; ROHS: Yes; Rated Current: 200MA; Rated Voltage: 40V; STATUS: Production
R43 = RES: RES MF 51 OHM 1/16W 1% 0402; AMBIQ_PN: AM-01-2166; DISTRIBUTOR: DIGIKEY; DISTRIBUTOR_PN: 541-51.0LCT-ND; HEIGHT: 0.40 MM; LEAD_FREE: Yes; MFG_NAME: VISHAY INTERTECHNOLOGY; MFG_PN: CRCW040251R0FKED; Manufacturer_Datasheet: http://www.vishay.com/docs/20035/dcrcwfre.pdf; PART_TYPE: 0402; Power Rating (Max) (W): 0.063W; ROHS: Yes; STATUS: Production; TOL: 1%
R44 R46 = RES: RES TF 10.0K 1/16W 1% 0402; AMBIQ_PN: AM-01-2777; DISTRIBUTOR: DIGIKEY; DISTRIBUTOR_PN: 311-10.0KLRCT-ND; HEIGHT: 0.40 MM; LEAD_FREE: Yes; MFG_NAME: YAGEO; MFG_PN: RC0402FR-0710KL; Manufacturer_Datasheet: http://www.yageo.com/documents/recent/PYu-RC0402_51_RoHS_L_6.pdf; Material (Resistor): TF; NUM_RESISTORS: 1; PART_TYPE: 0402; PCB_FOOTPRINT_OPTIONS: RC0402_25,RC0402_HD,RC0402_CC; PEAK_REFLOW_TEMP: 260; Power Rating (Max) (W): 0.063W; ROHS: Yes; STATUS: Production; TOL: 1%; Type: SMD
R45 = RES: RES MF 16.9K  1/16W 1% 0402; AMBIQ_PN: AM-01-0741; HEIGHT: 0.40 MM; LEAD_FREE: Yes; MFG_NAME: KOA SPEER; MFG_PN: RK73H1ETTP1692F; Manufacturer_Datasheet: http://www.koaspeer.com/pdfs/res5.pdf; PART_TYPE: 0402; Power Rating (Max) (W): 0.1W; ROHS: Yes; STATUS: Production; TOL: 1%
U14 = MAX44263: IC LIN AMP DUAL GP RRIO 15MHZ LN 1.8V - 5.5V SC70-8; AMBIQ_PN: AM-07-2165; DISTRIBUTOR: MOUSER; DISTRIBUTOR_PN: 700-MAX44263AXA+T; HEIGHT: 1.10MM; IC Type: Ultra high input impedance, low input cap, Op Amp; LEAD_FREE: Yes; MFG_NAME: MAXIM; Manufacturer_Datasheet: http://datasheets.maximintegrated.com/en/ds/MAX44260-MAX44263.pdf; PART_TYPE: AMPLIFIER; ROHS: Yes; STATUS: Production
C68-C71 = CAP_NP: CAP CER 0.1uF 16V 10% X7R 0402; AMBIQ_PN: AM-02-1045; DISTRIBUTOR: DIGIKEY; DISTRIBUTOR_PN: 587-1451-1-ND; Dielectric Material: X7R; HEIGHT: 0.55MM; LEAD_FREE: Yes; MFG_NAME: TAIYO YUDEN; MFG_PN: EMK105B7104KV-F; Manufacturer_Datasheet: http://www.yuden.co.jp/or/product/category/capacitor/EMK105B7104KV-F.pdf; PART_TYPE: CER\0402; Package Size: 0402; Package Type: SMD; ROHS: Yes; STATUS: Production; TOL: 10%; VOLTAGE: 16V
J17 = CONN_HDR_8X2: HDR 2x8 SMD 100MIL Female; AMBIQ_PN: AM-03-1296; DISTRIBUTOR: DIGIKEY; DISTRIBUTOR_PN: SAM14603TR-ND; HEIGHT: 7.37MM; LEAD_FREE: Yes; MFG_NAME: SAMTEC; Manufacturer_Datasheet: http://suddendocs.samtec.com/catalog_english/ssm_sm.pdf; PART_TYPE: HEADER; Package Type: SMD; ROHS: Yes; STATUS: Production
J18 = CONN_JACK_3P5MM: CON AUD JACK RA 3.5MM TH; AMBIQ_PN: AM-03-1268; DISTRIBUTOR: MOUSER; DISTRIBUTOR_PN: 490-SJ-435107; HEIGHT: 7.3MM; LEAD_FREE: Yes; MFG_NAME: CUI INC; Manufacturer_Datasheet: https://www.cui.com/product/resource/digikeypdf/sj-435107.pdf; PART_TYPE: JACK; Package Type: TH; ROHS: Yes; STATUS: Production

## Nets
GND: C1.2 C2.1 C3.1 C4.1 C5.1 C6.2 C7.2 C8.1 C9.1 C10.1 C11.1 C13.2 C14.2 C15.2 C16.2 C17.1 C18.2 C19.2 C20.1 C21.2 C22.2 C23.2 C24.2 C25.2 C26.2 C27.2 C60.1 C61.1 C62.1 C63.2 C65.1 C66.2 C67.1 D1.2(A) J1.3(GND) J1.4(GND) J1.5(GND) J1.6(GND) J13.3(A2) J13.5(A3) J13.9(A5) J13.15(A8) J13.17(A9) J13.19(A10) J17.1(A1) J17.2(B1) J17.7(A4) J17.8(B4) J17.9(A5) J17.13(A7) J17.14(B7) J18.1(G) J18.7(SHIELD1) J18.8(SHIELD2) J29.5 R8.2 R38.2 R39.1 R45.2 R46.2 R48.2 SB72.2 SB73.2 SB74.2 SW1.3(B1) SW1.4(B2) SW2.3(B1) SW2.4(B2) SW3.3(B1) SW3.4(B2) U1.B2(VSSP) U1.B5(VSSA) U1.B12(VSSAUDA) U1.D2(VSS) U1.E12(VSSAUDD) U1.H1(VSSB) U1.J10(VSS18) U1.L1(VSSVCO) U1.L2(VSSS) U1.L8(VSSAUSB) U1.M1(RFIOM) U1.M3(RFSUB) U14.4(VSS) Y1.2 Y1.4 ; also on sheet 1 2 3 4 5
VDD18: C17.2 U1.H10(VDD18) ; also on sheet 1
VDD_5V: C61.2 C62.2 C63.1 J17.16(B8) Q2.3(COLLECTOR) U14.8(VDD) ; also on sheet 1 3 4 5
VDD_DBG: C60.2 J13.1(A1) R5.2 R6.2 R37.1 SB47.2 SB48.2
VDD_EXT: J17.15(A8) ; also on sheet 1 2 4 5
VDD_MCU_TRACK: C64.1 C66.1 C67.2 D7.2(A) Q2.2(EMITTER) R46.1 SB47.1 U14.6(INB-) ; also on sheet 1
VDDA: C12.1 C13.1 C14.1 C16.1 R7.2 R44.1 SB48.1 U1.B1(VDDP) U1.C4(VDDA) U1.M10(VDDH) ; also on sheet 1 4 5
VDDAUDA: C18.1 J17.10(B5) U1.B11(VDDAUDA) ; also on sheet 1
VDDAUDD: C19.1 U1.E11(VDDAUDD) ; also on sheet 1
VDDB: C27.1 U1.G1(VDDB) ; also on sheet 1
VDDBH: C6.1 L2.2 R4.2 TP1.1(Pin1) U1.G12(VDDBH)
VDDBH_RF: C20.2 R4.1 U1.J1(VDDBH_RF)
VDDC: C24.1 TP9.1(Pin1) U1.A3(VDDC)
VDDC_LV: R8.1 U1.B3(VDDC_LV)
VDDF: C12.2 C25.1 TP8.1(Pin1) U1.C2(VDDF)
VDDH2: C15.1 U1.M9(VDDH2) ; also on sheet 1 4 5
VDDS: C26.1 U1.C1(VDDS)
VDDUSB0P9: C21.1 U1.L7(VDDUSB0P9) ; also on sheet 1
VDDUSB33: C22.1 U1.K7(VDDUSB33) ; also on sheet 1
ADC0_CTS23_I2S1DIN_GP19: SB2.1 U1.C3(GPIO19) ; also on sheet 4 5
ADC1_I2S1WS_CTS01_GP18: SB1.1 U1.D3(GPIO18) ; also on sheet 4 5
ADC2_I2S1DAT_RTS3_I2S1DOUT_GP17: U1.D4(GPIO17) ; also on sheet 4 5
ADC3_I2S1CK_RTS1_GP16: U1.D7(GPIO16) ; also on sheet 4 5
ADC4_RX3_REFCLK_GP15: U1.E5(GPIO15) ; also on sheet 4 5
ADC5_RX1_I2S0DIN_GP14: U1.D6(GPIO14) ; also on sheet 4 5
ADC6_I2S0WS_TX23_GP13: U1.D5(GPIO13) ; also on sheet 4 5
ADC7_I2S0DAT_TX01_CMRF2_I2S0DOUT_GP12: U1.B4(GPIO12) ; also on sheet 4 5
AP4_USBN: U1.M8(USB0PN) ; also on sheet 3
AP4_USBP: U1.M7(USB0PP) ; also on sheet 3
AT_3.3V: J29.1 ; also on sheet 1 2
AT_SWO: J13.6(B3) SB40.1 SB41.1 ; also on sheet 2
AT_SWRST: C9.2 D1.1(C) J13.10(B5) R7.1 SW3.1(A1) SW3.2(A2) U1.A6(RSTN) ; also on sheet 2 4 5
CMIN0_M1MISO_TE_GP10: U1.E6(GPIO10) ; also on sheet 4 5
CMIN1_I2S0CK_RX23_GP11: U1.E4(GPIO11) ; also on sheet 4 5
CMRF0_M1SDA_M1MOSI_GP9: U1.E7(GPIO9) ; also on sheet 4 5
CMRF1_M1SCL_M1SCK_GP8: U1.E8(GPIO8) ; also on sheet 4 5
CTS01_GP59: U1.J8(GPIO59) ; also on sheet 2 4 5
D0N: C69.2 SB50.2 SB63.1 SB64.1 SB73.1
D0P: C68.2 SB49.2 SB62.1 SB67.1
D1N: C71.2 SB52.2 SB70.1 SB71.1 SB72.1
D1P: C70.2 SB51.2 SB68.1 SB69.1 SB74.1
DISPCM_GP89: U1.F10(GPIO89) ; also on sheet 4
HDR_LPADC_D0N_SE0: J17.6(B3) SB63.2
HDR_LPADC_D0P_SE1: J17.4(B2) SB67.2
HDR_LPADC_D1N_SE2: J17.5(A3) SB70.2
HDR_LPADC_D1P_SE3: J17.3(A2) SB69.2
JLINK_nRST: J29.3 ; also on sheet 2
JLINK_SWCLK: J29.4 ; also on sheet 2
JLINK_SWDIO: J29.2 ; also on sheet 2
JLINK_SWO: J29.6 ; also on sheet 2
LPADC_D0N_SE0: C69.1 SB50.1 U1.A10(LPADCD0NSE0)
LPADC_D0P_SE1: C68.1 SB49.1 U1.A11(LPADCD0PSE1)
LPADC_D1N_SE2: C71.1 SB52.1 U1.C11(LPADCD1NSE2)
LPADC_D1P_SE3: C70.1 SB51.1 U1.D11(LPADCD1PSE3)
LPADC_REF: C1.1 U1.A12(LPADC_VREF)
LPMICBIAS: C23.1 J17.11(A6) J17.12(B6) U1.B10(LPMICBIAS)
M0MISO_I2S0WS_CTS23_GP7: U1.J6(GPIO7) ; also on sheet 4
M0SCL_M0SCK_I2S0CK_RTS23_GP5: U1.H4(GPIO5) ; also on sheet 4
M0SDA_M0MOSI_I2S0DAT_CTS01_I2S0DOUT_GP6: U1.J5(GPIO6) ; also on sheet 4
M2MISO_DSPTCK_I2S0DIN_GP27: U1.M5(GPIO27) ; also on sheet 4
M2SCL_M2SCK_DSPTMS_GP25: U1.K5(GPIO25) ; also on sheet 4
M2SDA_M2MOSI_DSPTCK_GP26: U1.L5(GPIO26) ; also on sheet 4
M3MISO_CKO_RX2_TE_GP33: U1.G3(GPIO33) ; also on sheet 4 5
M3SCL_M3SCK_TX2_GP31: U1.H2(GPIO31) ; also on sheet 4 5
M3SDA_M3MOSI_RX0_GP32: U1.G2(GPIO32) ; also on sheet 4 5
M5MISO_I2S1WS_RTS01_GP49: U1.D1(GPIO49) ; also on sheet 4 5
M5SCL_M5SCK_I2S1CK_RX01_GP47: U1.F1(GPIO47) ; also on sheet 2 4 5
M5SDA_M5MOSI_I2S1DAT_RX23_I2S1DOUT_GP48: U1.E1(GPIO48) ; also on sheet 4 5
M6MISO_CKO_I2S1WS_RX23_TE_GP63: U1.M6(GPIO63) ; also on sheet 4 5
M6SCL_M6SCK_I2S1CK_TX23_GP61: U1.K6(GPIO61) ; also on sheet 4 5
M6SDA_M6MOSI_I2S1DAT_RX01_I2S1DOUT_GP62: U1.L6(GPIO62) ; also on sheet 4 5
M7MISO_SWO_RTS01_GP24: U1.E2(GPIO24) ; also on sheet 4 5
M7SCL_M7SCK_SWO_RX01_GP22: U1.F3(GPIO22) ; also on sheet 4 5
M7SDA_M7MOSI_SWO_RX23_GP23: U1.F2(GPIO23) ; also on sheet 4 5
MIPI_CLKN: U1.J12(MIPI_CLKN) ; also on sheet 4
MIPI_CLKP: U1.K12(MIPI_CLKP) ; also on sheet 4
MIPI_D0N: U1.L12(MIPI_D0N) ; also on sheet 4
MIPI_D0P: U1.M12(MIPI_D0P) ; also on sheet 4
MSPI00_32KXT_RTS0_DISPD0_I2S1DIN_GP64: U1.B6(GPIO64) ; also on sheet 4
MSPI01_32KXT_CTS0_DISPD1_GP65: U1.A7(GPIO65) ; also on sheet 4
MSPI02_CKO_TX0_DISPD2_GP66: U1.A8(GPIO66) ; also on sheet 4
MSPI03_CKO_TX2_DISPD3_GP67: U1.C6(GPIO67) ; also on sheet 4
MSPI04_SWO_RX0_DISPD4_GP68: U1.B7(GPIO68) ; also on sheet 4
MSPI05_32KXT_SWO_RX2_DISPD5_GP69: U1.B8(GPIO69) ; also on sheet 4
MSPI06_32KXT_SWTR0_RTS0_DISPD6_GP70: U1.C5(GPIO70) ; also on sheet 4
MSPI07_CKO_SWTR1_CTS0_DISPD7_GP71: U1.C7(GPIO71) ; also on sheet 4
MSPI08_CKO_SWTR2_TX0_DISPD8_GP72: U1.C8(GPIO72) ; also on sheet 4
MSPI09_SWTR3_TX2_DISPD9_GP73: U1.D8(GPIO73) ; also on sheet 4
MSPI10_32KXT_RX2_DISPD15_GP37: U1.F11(GPIO37) ; also on sheet 4
MSPI11_SWTRCK_RTS0_DISPD16_GP38: U1.F12(GPIO38) ; also on sheet 4 5
MSPI20_QSPID0_RX0_DISPD10_DSPISD_GP74: U1.G11(GPIO74) ; also on sheet 4
MSPI21_QSPID1_RX2_DISPD11_DSPIDCX_GP75: U1.H11(GPIO75) ; also on sheet 4
MSPI22_QSPID2_RTS0_DISPD12_GP76: U1.J11(GPIO76) ; also on sheet 4
MSPI23_QSPID3_CTS0_DISPD13_GP77: U1.K11(GPIO77) ; also on sheet 4
MSPI24_QSPISCK_DISPD14_DSPISCK_GP78: U1.L11(GPIO78) ; also on sheet 4
MSPI25_SDIFD4_SWO_DISPVS_GP79: U1.M11(GPIO79) ; also on sheet 4
MSPI26_CKO_SDIFD5_SWTR0_DISPHS_GP80: U1.K10(GPIO80) ; also on sheet 4
MSPI27_CKO_SDIFD6_SWTR1_DISPDE_GP81: U1.L10(GPIO81) ; also on sheet 4
MSPI28_32KXT_SDIFD7_SWTR2_DISPPCK_GP82: U1.L9(GPIO82) ; also on sheet 4
MSPI29_32KXT_SDIFCMD_SWTR3_DISPSD_GP83: U1.K9(GPIO83) ; also on sheet 4
PDM0CK_SWTRCK_RTS23_TE_GP50: R40.2 U1.A9(GPIO50) ; also on sheet 4
PDM0DAT_SWTR0_CTS01_GP51: J13.14(B7) U1.B9(GPIO51) ; also on sheet 4
PDM1CK_SWTR1_CTS23_VCO_GP52: J13.16(B8) U1.C10(GPIO52) ; also on sheet 4
PDM1DAT_SWTR2_TX01_GP53: J13.18(B9) U1.C9(GPIO53) ; also on sheet 4
PDM2CK_SWTR3_TX23_GP54: J13.20(B10) U1.D10(GPIO54) ; also on sheet 4
PDM2DAT_SWTRCTL_RX01_GP55: SB41.2 U1.D9(GPIO55) ; also on sheet 4
PDM3CK_SWO_RX23_GP56: U1.E10(GPIO56) ; also on sheet 4
PDM3DAT_SWO_RTS01_VCO_GP57: U1.E9(GPIO57) ; also on sheet 4
RING: J18.3(R) SB64.2 SB68.2
RTS03_GP58: U1.J7(GPIO58) ; also on sheet 2 4 5
SDIFCK0_GP88: U1.F9(GPIO88) ; also on sheet 4
SDIFD0_GP84: U1.J9(GPIO84) ; also on sheet 4
SDIFD1_GP85: U1.H9(GPIO85) ; also on sheet 4
SDIFD2_GP86: U1.G10(GPIO86) ; also on sheet 4
SDIFD3_TE_GP87: U1.G9(GPIO87) ; also on sheet 4
SIMOSW: L1.1 U1.A1(SIMOBUCK_SW)
SIMOSWSEL: L1.2 U1.A2(SIMOBUCK_SWSEL)
SWDCK_TX01_GP20: J13.4(B2) R39.2 U1.K3(GPIO20/SWDCK) ; also on sheet 2
SWDIO_TX23_GP21: J13.2(B1) R37.2 U1.J3(GPIO21/SWDIO) ; also on sheet 2
SWO_VCO_IS20CK_DSPTDO_GP28: SB40.2 U1.E3(GPIO28) ; also on sheet 4
TIP: J18.2(L) SB62.2 SB71.2
TRC0_SSDA_SMOSI_TX23_VCO_GP1: U1.J4(GPIO1) ; also on sheet 4 5
TRC1_SMISO_TRIG1_RX01_VCO_GP2: U1.K4(GPIO2) ; also on sheet 4 5
TRC2_SCEn_SWO_RX23_GP3: U1.L4(GPIO3) ; also on sheet 4 5
TRC3_SINT_32KXT_RTS01_I2S0DIN_GP4: U1.M4(GPIO4) ; also on sheet 4 5
TRCLK_SSCL_SSCK_TX01_VCO_GP0: U1.H3(GPIO0) ; also on sheet 4 5
TRIG0_VCO_I2S0DAT_CTS1_DSPTRSTN_I2S0DOUT_GP29: U1.F4(GPIO29) ; also on sheet 4
TRIG1_VCO_I2S0WS_TX0_DSPTDI_GP30: U1.G4(GPIO30) ; also on sheet 1 4 5
TX0_CTS3_GP60: U1.K8(GPIO60) ; also on sheet 2 4 5
TXEN: U1.K1(TXEN) ; also on sheet 4 5
VCO_GP90: U1.J2(GPIO90) ; also on sheet 1 4 5
VCO_GP91: U1.K2(GPIO91) ; also on sheet 1 4 5
N12525: L2.1 U1.H12(VDDBH_SW)
N12956: C10.2 U1.A5(XO) Y2.2
N12964: C11.2 U1.A4(XI) Y2.1
N13851: C7.1 U1.D12(XO32M) Y1.1
N13855: C8.2 U1.C12(XI32M) Y1.3
N15152: C4.2 R2.2 R3.1
N15160: C5.2 R3.2 U1.M2(RFIOP)
N591950: J13.11(A6) J13.13(A7) R38.1
N592180: J13.12(B6) R40.1
N604126: R43.1 R45.1 U14.5(INB+)
N604165: R43.2 U14.1(OUTB) U14.2(INB-)
N604317: C65.2 R44.2 U14.3(INB+)
N612079: C64.2 D7.1(C) Q2.1(BASE) U14.7(OUTB)
N663537: J18.4(MIC) R48.1
N685974: C3.2 J1.2(OUT) R1.1
N685989: A1.1 C2.2 R1.2
N693191: R5.1 SB1.2 SW1.1(A1) SW1.2(A2)
N693245: R6.1 SB2.2 SW2.1(A1) SW2.2(A2)
N1187624: J1.1(IN) R2.1

Not connected (* = marked no-connect by the designer): J13 7(A4)* 8(B4)*; J18 5(NC1)* 6(NC2)*; SS1 1(NC)*; SS2 1(NC)*; SS3 1(NC)*; SS4 1(NC)*

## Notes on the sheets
sheet 8
- LPADC 3.5MM Jack
- ROUTE LPADC_D1N_SE2 AND
  LPADC_D1P_SE3 AS DIFFERENTIAL
  PAIR
- ROUTE LPADC_D0N_SE0 AND
  LPADC_D0P_SE1 AS DIFFERENTIAL
  PAIR
- LPADC Voltage Header
sheet 9
- AMA4B2KK-KBR-B2
- AMA4B2KK-KBR-B2
- ROUTE USB0PN AND
  USB0PP AS 90 OHM
  DIFFERENTIAL PAIR
- ROUTE MIPI_CLKN AND
  MIPI_CLKP AS 100 OHM
  DIFFERENTIAL PAIR AND 50
  OHM SINGLE ENDED TRACES
- ROUTE MIPI_D0N AND
  MIPI_D0P AS 100 OHM
  DIFFERENTIAL PAIR AND 50
  OHM SINGLE ENDED TRACES
- Apollo4 has on-chip
  matching, but optional
  external matching can be
  used, dependent upon
  antenna impedance
- ROUTE RFIOP
  AS 50 OHM
  SINGLE ENDED
  IMPEDANCE
- 6pF CL crystal
- 32MHz crystal load
  caps are integrated,
  but recommended
  to keep option
  for external caps.
- DECOUPLING  CAPACITORS
- POWER SUPPLY CONNECTIONS
- Push Buttons
- PLACE CAPS AS CLOSE AS POSSIBLE TO CHIP
- PLACE CAPS AS CLOSE AS POSSIBLE TO CHIP
- Stand-Offs
- nRST Push Button
- TEST POINTS
- PLACE CAPS AS CLOSE AS POSSIBLE TO CHIP
sheet 10
- Debug-In Header
- J-Link Programmer
